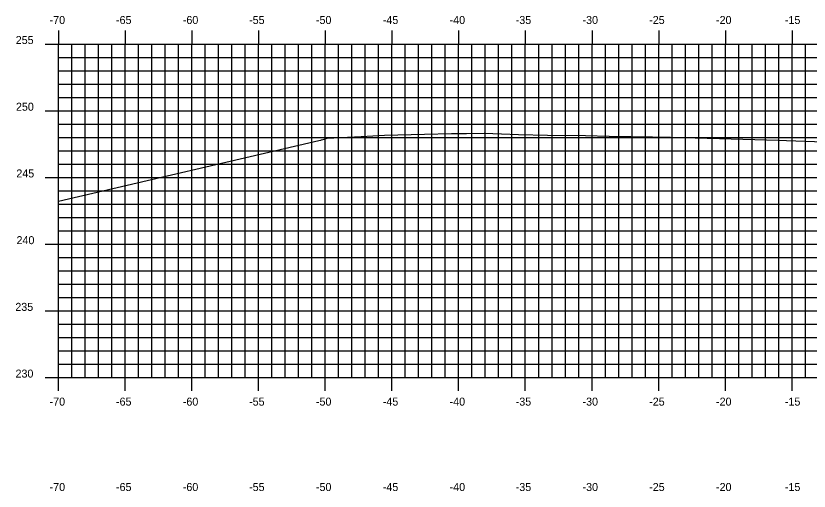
# Model space of a CAD drawing. Extents: x 1170543 to 1177585, y 609599 to 610623.
# Drawn here: x 1172105.6 to 1172165, y 610339.3 to 610374.9 of the extents above; entities that cross this region are included whole.
import ezdxf

# ---------------------------------------------------------------- set-up
doc = ezdxf.new("R2010")
doc.units = 0
for name, color, linetype in [('H_V ANNOTATION', 7, 'Continuous'), ('MAJOR', 7, 'Continuous'), ('MINOR', 7, 'Continuous'), ('S_Roadway_Centerline', 7, 'Continuous')]:
    doc.layers.add(name, color=color, linetype=linetype)

msp = doc.modelspace()

# ---------------------------------------------------------------- linework, layer by layer
at = {"layer": 'MAJOR'}
for p, q in [((1172108.767, 610373.803), (1172108.767, 610372.801)), ((1172113.767, 610373.803), (1172113.767, 610372.801)), ((1172118.767, 610373.803), (1172118.767, 610372.801)), ((1172123.767, 610373.803), (1172123.767, 610372.801)), ((1172128.767, 610373.803), (1172128.767, 610372.801)), ((1172133.767, 610373.803), (1172133.767, 610372.801)), ((1172138.767, 610373.803), (1172138.767, 610372.801)), ((1172143.767, 610373.803), (1172143.767, 610372.801)), ((1172148.767, 610373.803), (1172148.767, 610372.801)), ((1172153.767, 610373.803), (1172153.767, 610372.801)), ((1172158.767, 610373.803), (1172158.767, 610372.801)), ((1172163.767, 610373.803), (1172163.767, 610372.801)), ((1172107.765, 610372.801), (1172108.767, 610372.801)), ((1172108.767, 610372.801), (1172248.767, 610372.801)), ((1172108.767, 610347.801), (1172108.767, 610372.801)), ((1172108.767, 610347.801), (1172108.767, 610372.801)), ((1172108.767, 610372.801), (1172248.767, 610372.801)), ((1172113.767, 610347.801), (1172113.767, 610372.801)), ((1172118.767, 610347.801), (1172118.767, 610372.801)), ((1172123.767, 610347.801), (1172123.767, 610372.801)), ((1172128.767, 610347.801), (1172128.767, 610372.801)), ((1172133.767, 610347.801), (1172133.767, 610372.801)), ((1172138.767, 610347.801), (1172138.767, 610372.801)), ((1172143.767, 610347.801), (1172143.767, 610372.801)), ((1172148.767, 610347.801), (1172148.767, 610372.801)), ((1172153.767, 610347.801), (1172153.767, 610372.801)), ((1172158.767, 610347.801), (1172158.767, 610372.801)), ((1172163.767, 610347.801), (1172163.767, 610372.801)), ((1172107.765, 610367.801), (1172108.767, 610367.801)), ((1172108.767, 610367.801), (1172248.767, 610367.801)), ((1172107.765, 610362.801), (1172108.767, 610362.801)), ((1172108.767, 610362.801), (1172248.767, 610362.801)), ((1172107.765, 610357.801), (1172108.767, 610357.801)), ((1172108.767, 610357.801), (1172248.767, 610357.801)), ((1172107.765, 610352.801), (1172108.767, 610352.801)), ((1172108.767, 610352.801), (1172248.767, 610352.801)), ((1172107.765, 610347.801), (1172108.767, 610347.801)), ((1172108.767, 610347.801), (1172248.767, 610347.801)), ((1172108.767, 610347.801), (1172248.767, 610347.801)), ((1172108.767, 610346.799), (1172108.767, 610347.801)), ((1172113.767, 610346.799), (1172113.767, 610347.801)), ((1172118.767, 610346.799), (1172118.767, 610347.801)), ((1172123.767, 610346.799), (1172123.767, 610347.801)), ((1172128.767, 610346.799), (1172128.767, 610347.801)), ((1172133.767, 610346.799), (1172133.767, 610347.801)), ((1172138.767, 610346.799), (1172138.767, 610347.801)), ((1172143.767, 610346.799), (1172143.767, 610347.801)), ((1172148.767, 610346.799), (1172148.767, 610347.801)), ((1172153.767, 610346.799), (1172153.767, 610347.801)), ((1172158.767, 610346.799), (1172158.767, 610347.801)), ((1172163.767, 610346.799), (1172163.767, 610347.801))]:
    msp.add_line(p, q, dxfattribs=at)
at = {"layer": 'MINOR'}
for p, q in [((1172109.767, 610347.801), (1172109.767, 610372.801)), ((1172110.767, 610347.801), (1172110.767, 610372.801)), ((1172111.767, 610347.801), (1172111.767, 610372.801)), ((1172112.767, 610347.801), (1172112.767, 610372.801)), ((1172114.767, 610347.801), (1172114.767, 610372.801)), ((1172115.767, 610347.801), (1172115.767, 610372.801)), ((1172116.767, 610347.801), (1172116.767, 610372.801)), ((1172117.767, 610347.801), (1172117.767, 610372.801)), ((1172119.767, 610347.801), (1172119.767, 610372.801)), ((1172120.767, 610347.801), (1172120.767, 610372.801)), ((1172121.767, 610347.801), (1172121.767, 610372.801)), ((1172122.767, 610347.801), (1172122.767, 610372.801)), ((1172124.767, 610347.801), (1172124.767, 610372.801)), ((1172125.767, 610347.801), (1172125.767, 610372.801)), ((1172126.767, 610347.801), (1172126.767, 610372.801)), ((1172127.767, 610347.801), (1172127.767, 610372.801)), ((1172129.767, 610347.801), (1172129.767, 610372.801)), ((1172130.767, 610347.801), (1172130.767, 610372.801)), ((1172131.767, 610347.801), (1172131.767, 610372.801)), ((1172132.767, 610347.801), (1172132.767, 610372.801)), ((1172134.767, 610347.801), (1172134.767, 610372.801)), ((1172135.767, 610347.801), (1172135.767, 610372.801)), ((1172136.767, 610347.801), (1172136.767, 610372.801)), ((1172137.767, 610347.801), (1172137.767, 610372.801)), ((1172139.767, 610347.801), (1172139.767, 610372.801)), ((1172140.767, 610347.801), (1172140.767, 610372.801)), ((1172141.767, 610347.801), (1172141.767, 610372.801)), ((1172142.767, 610347.801), (1172142.767, 610372.801)), ((1172144.767, 610347.801), (1172144.767, 610372.801)), ((1172145.767, 610347.801), (1172145.767, 610372.801)), ((1172146.767, 610347.801), (1172146.767, 610372.801)), ((1172147.767, 610347.801), (1172147.767, 610372.801)), ((1172149.767, 610347.801), (1172149.767, 610372.801)), ((1172150.767, 610347.801), (1172150.767, 610372.801)), ((1172151.767, 610347.801), (1172151.767, 610372.801)), ((1172152.767, 610347.801), (1172152.767, 610372.801)), ((1172154.767, 610347.801), (1172154.767, 610372.801)), ((1172155.767, 610347.801), (1172155.767, 610372.801)), ((1172156.767, 610347.801), (1172156.767, 610372.801)), ((1172157.767, 610347.801), (1172157.767, 610372.801)), ((1172159.767, 610347.801), (1172159.767, 610372.801)), ((1172160.767, 610347.801), (1172160.767, 610372.801)), ((1172161.767, 610347.801), (1172161.767, 610372.801)), ((1172162.767, 610347.801), (1172162.767, 610372.801)), ((1172164.767, 610347.801), (1172164.767, 610372.801)), ((1172108.767, 610371.801), (1172248.767, 610371.801)), ((1172108.767, 610371.801), (1172109.769, 610371.801)), ((1172108.767, 610370.801), (1172248.767, 610370.801)), ((1172108.767, 610370.801), (1172109.769, 610370.801)), ((1172108.767, 610369.801), (1172248.767, 610369.801)), ((1172108.767, 610369.801), (1172109.769, 610369.801)), ((1172108.767, 610368.801), (1172248.767, 610368.801)), ((1172108.767, 610368.801), (1172109.769, 610368.801)), ((1172108.767, 610366.801), (1172248.767, 610366.801)), ((1172108.767, 610366.801), (1172109.769, 610366.801)), ((1172108.767, 610365.801), (1172248.767, 610365.801)), ((1172108.767, 610365.801), (1172109.769, 610365.801)), ((1172108.767, 610364.801), (1172248.767, 610364.801)), ((1172108.767, 610364.801), (1172109.769, 610364.801)), ((1172108.767, 610363.801), (1172248.767, 610363.801)), ((1172108.767, 610363.801), (1172109.769, 610363.801)), ((1172108.767, 610361.801), (1172248.767, 610361.801)), ((1172108.767, 610361.801), (1172109.769, 610361.801)), ((1172108.767, 610360.801), (1172248.767, 610360.801)), ((1172108.767, 610360.801), (1172109.769, 610360.801)), ((1172108.767, 610359.801), (1172248.767, 610359.801)), ((1172108.767, 610359.801), (1172109.769, 610359.801)), ((1172108.767, 610358.801), (1172248.767, 610358.801)), ((1172108.767, 610358.801), (1172109.769, 610358.801)), ((1172108.767, 610356.801), (1172248.767, 610356.801)), ((1172108.767, 610356.801), (1172109.769, 610356.801)), ((1172108.767, 610355.801), (1172248.767, 610355.801)), ((1172108.767, 610355.801), (1172109.769, 610355.801)), ((1172108.767, 610354.801), (1172248.767, 610354.801)), ((1172108.767, 610354.801), (1172109.769, 610354.801)), ((1172108.767, 610353.801), (1172248.767, 610353.801)), ((1172108.767, 610353.801), (1172109.769, 610353.801)), ((1172108.767, 610351.801), (1172248.767, 610351.801)), ((1172108.767, 610351.801), (1172109.769, 610351.801)), ((1172108.767, 610350.801), (1172248.767, 610350.801)), ((1172108.767, 610350.801), (1172109.769, 610350.801)), ((1172108.767, 610349.801), (1172248.767, 610349.801)), ((1172108.767, 610349.801), (1172109.769, 610349.801)), ((1172108.767, 610348.801), (1172248.767, 610348.801)), ((1172108.767, 610348.801), (1172109.769, 610348.801))]:
    msp.add_line(p, q, dxfattribs=at)
at = {"layer": 'S_Roadway_Centerline'}
msp.add_lwpolyline([(1172108.767, 610361.012), (1172128.287, 610365.574), (1172128.438, 610365.603), (1172128.495, 610365.614), (1172128.696, 610365.666), (1172128.919, 610365.735), (1172131.47, 610365.872), (1172133.222, 610365.98), (1172136.212, 610366.05), (1172138.242, 610366.096), (1172139.361, 610366.103), (1172140.677, 610366.11), (1172141.989, 610366.062), (1172143.262, 610366.016), (1172145.431, 610365.982), (1172148.282, 610365.938), (1172150.04, 610365.906), (1172153.302, 610365.845), (1172154.648, 610365.812), (1172158.322, 610365.718), (1172162.72, 610365.596), (1172163.342, 610365.579), (1172168.235, 610365.398)], dxfattribs=at)

# ---------------------------------------------------------------- texts
at = {"layer": 'H_V ANNOTATION'}
for s, p in [('-70', (1172108.109, 610374.301)), ('-65', (1172113.085, 610374.301)), ('-60', (1172118.093, 610374.301)), ('-55', (1172123.063, 610374.301)), ('-50', (1172128.071, 610374.301)), ('-45', (1172133.085, 610374.301)), ('-40', (1172138.093, 610374.301)), ('-35', (1172143.047, 610374.301)), ('-30', (1172148.055, 610374.301)), ('-25', (1172153.052, 610374.301)), ('-20', (1172158.061, 610374.301)), ('-15', (1172163.224, 610374.301)), ('255', (1172105.57, 610372.801)), ('250', (1172105.586, 610367.801)), ('245', (1172105.613, 610362.801)), ('240', (1172105.629, 610357.801)), ('235', (1172105.538, 610352.801)), ('230', (1172105.554, 610347.801)), ('-70', (1172108.109, 610345.701)), ('-65', (1172113.085, 610345.701)), ('-60', (1172118.093, 610345.701)), ('-55', (1172123.063, 610345.701)), ('-50', (1172128.071, 610345.701)), ('-45', (1172133.085, 610345.701)), ('-40', (1172138.093, 610345.701)), ('-35', (1172143.047, 610345.701)), ('-30', (1172148.055, 610345.701)), ('-25', (1172153.052, 610345.701)), ('-20', (1172158.061, 610345.701)), ('-15', (1172163.224, 610345.701)), ('-70', (1172108.109, 610339.301)), ('-65', (1172113.085, 610339.301)), ('-60', (1172118.093, 610339.301)), ('-55', (1172123.063, 610339.301)), ('-50', (1172128.071, 610339.301)), ('-45', (1172133.085, 610339.301)), ('-40', (1172138.093, 610339.301)), ('-35', (1172143.047, 610339.301)), ('-30', (1172148.055, 610339.301)), ('-25', (1172153.052, 610339.301)), ('-20', (1172158.061, 610339.301)), ('-15', (1172163.224, 610339.301))]:
    msp.add_text(s, height=0.6, dxfattribs=at).set_placement(p)

doc.saveas('drawing.dxf')
